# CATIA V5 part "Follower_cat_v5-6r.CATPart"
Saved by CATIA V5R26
Part number: Follower
Bounding box of the stored display mesh (mm): x -9.942 to 9.942, y -9.942 to 9.942, z 0 to 100
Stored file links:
  D:\_Deepak\CATIA\CATIA V5 2015 Parts Files\Tutorial Files\Tutorials\c16_catia_v5_6r2016_tut\Cam Follower mechanism\Follower_cat_v5-6r2012.CATPart
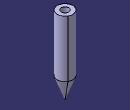
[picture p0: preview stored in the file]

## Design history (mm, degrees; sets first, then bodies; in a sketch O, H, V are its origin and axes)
Body1 (main body)
  Sketch1 on yz-plane, origin (0, 0, 0), H (0, 1, 0), V (0, 0, 1)
    line L1 (0, 0) -> (10, 27.4748)
    point P1 (10, 27.4748)
    line L2 (10, 27.4748) -> (10, 100)
    point P2 (10, 27.4748)
    point P3 (10, 100)
    point P4 (0, 100)
    point P5 (10, 91.3901)
    line L3 (0, 0) -> (0, 100)
    reference intersected line E1 through (0, 0) direction (-1, 0) from xy-plane
    reference intersected line E3 through (0, 0) direction (0, 1) from zx-plane
    line L4 (0, 100) -> (10, 100)
    point P6 (10, 100)
    angle L1 L3 = 20
    distance O P4 = 100
    length L4 = 10
    coincidence: P2 L1, P4 V, P5 L2, P2 P1, E3 P4, P1 L2, P6 L2, P6 P3
    vertical: L2 V, L3 V, E3 V
    horizontal: E1 H, L4 H
    perpendicularity: E1 L2
  Shaft1: profile Sketch1, axis Sketch1.L3, angle 360
  Sketch2 on face of Shaft1 from Sketch1.L4, origin (0, 0, 100), H (1, 0, 0), V (0, 1, 0)
    point P1 (0, 0)
  Hole1: placed by Sketch2, at (0, 0, 100) direction (0, 0, -1), diameter 10, depth 55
